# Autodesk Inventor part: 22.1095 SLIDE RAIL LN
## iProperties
Created: 2007-06
Part Number: 22.1095 SLIDE RAIL LN
Material: UHMW, Black
Document SubType Name: Modeling
Designer: Andy Moles
Density: 0.94 g/cm^3
Author: Andy Moles
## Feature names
1. Extrusion1
2. Extrusion2
3. Extrusion3
4. Mirror1
